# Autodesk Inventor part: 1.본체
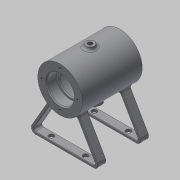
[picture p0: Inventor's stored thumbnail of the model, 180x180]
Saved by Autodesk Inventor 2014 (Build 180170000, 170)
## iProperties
Created: 2016-03
Part Number: 1.본체
Material: 일반
Document SubType Name: Modeling
Designer: SCD-A15
Density: 1 g/cm^3
Appearance: 기본값
Author: SCD-A15
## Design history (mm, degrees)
sketch "스케치1"
  geometry: C1 r 26 at (0, 0); 1 further point
  constraints: 1 centre point, 1 coincident
  dimensions: "d0" = 52 diameter of C1
extrude "돌출1" new body sketch "스케치1" stored distance "d1" = 70; taper "d2" = 0 deg
node "작업 평면1"
sketch "스케치3"
  geometry: L1 (0, 8.775)-(42.594, -65); L2 (42.594, -65)-(-42.594, -65); L3 (-42.594, -65)-(0, 8.775); L4 (0, 0)-(0, -26); L5 (37.398, -62)-(0, 2.775); L6 (0, 2.775)-(-37.398, -62); L7 (-37.398, -62)-(37.398, -62); A1 r 26 centre (0, 0) between (16.613, -20) and (0, -26) reference; 2 further points
  constraints: 14 end point, 2 point on circle, 1 coincident, 1 perpendicular, 1 point on line, 1 vertical, 1 vertical alignment, 9 other
  dimensions: "d4" = 65 distance from line of L2 point (0, 0); "d5" = 45 distance from line of L2 A1.start; "d6" = 3 distance between parallel lines of L1 L5
extrude "돌출2" join sketch "스케치3" distance "d7" = 10; taper "d8" = 0 deg
fillet "모깎기1" dims "d9" = 5
fillet "모깎기2" dims "d10" = 2
sketch "스케치10"
  geometry: L1 (0, 10)-(67.868, 10) reference; C1 r 3 at (13.934, 5); C2 r 3 at (53.934, 5); 1 further point
  constraints: 2 centre point, 1 equal radius, 1 horizontal alignment
  dimensions: "d76" = 20 horizontal distance of C1.centre point (33.934, 30); "d77" = 40 distance of C2.centre C1.centre; "d78" = 5 distance from line of L1 C2.centre; "d79" = 6 diameter of C2
extrude "돌출5" cut sketch "스케치10" stored distance "d80" = 29; taper "d81" = 0 deg
fillet "모깎기4" dims "d82" = 0.5
sketch "스케치5"
  geometry: C1 r 5 at (0, 0); 1 further point
  constraints: 1 centre point, 1 coincident
  dimensions: "d11" = 10 diameter of C1
extrude "돌출3" join sketch "스케치5" distance "d12" = 29; taper "d13" = 0 deg
sketch "스케치6"
  geometry: L1 (0, 0)-(7.506, -28.012); L2 (0, 0)-(0, -26); 2 further points
  constraints: 4 end point, 1 coincident, 1 vertical, 1 vertical alignment, 1 other
  dimensions: "d14" = 15 deg angle of L2 L1; "d15" = 29 distance of L1.start L1.end
node "작업 평면2"
sketch "스케치7"
  geometry: C1 r 6 at (0, 0); 1 further point
  constraints: 1 centre point, 1 coincident
  dimensions: "d16" = 12 diameter of C1
extrude "돌출4" join sketch "스케치7" stored distance "d17" = 29; taper "d18" = 0 deg
hole "구멍1" diameter "d21" = 28; stored, may be unused: countersink angle "d25" = 90 deg, drill point angle "d27" = 118 deg; dims "d19" = 10, "d20" = 10, "d22" = 6, "d23" = 32, "d24" = 12, "d26" = 8
hole "구멍2" diameter "d30" = 28; stored, may be unused: countersink angle "d34" = 90 deg, drill point angle "d36" = 118 deg; dims "d28" = 10, "d29" = 10, "d31" = 6, "d32" = 32, "d33" = 12, "d35" = 8
sketch "스케치8"
  geometry: C1 r 16 at (0, 0) reference; 1 further point
  constraints: 1 vertical alignment
  dimensions: "d90" = 21 distance of C1.centre point (0, 21)
hole "구멍3" sketch "스케치8" at (0, 21) diameter "d37" = 3.242; stored, may be unused: countersink angle "d41" = 90 deg, drill point angle "d43" = 118 deg; dims "d38" = 8, "d39" = 32, "d40" = 12, "d42" = 10
sketch "스케치9"
  geometry: L1 (0, 21)-(18, 21); L2 (21, 18)-(21, -18); L3 (18, -21)-(0, -21); L4 (0, -21)-(0, 21); A1 r 3 centre (18, -18) between (18, -21) and (21, -18); A2 r 3 centre (18, 18) between (21, 18) and (18, 21); 4 further points
  constraints: 8 end point, 4 point on circle, 4 point on line, 4 tangent, 2 centre point, 2 parallel, 1 coincident, 1 equal radius, 1 horizontal, 1 midpoint, 1 perpendicular
  dimensions: "d47" = 42 distance of point (21, 21) point (21, -21); "d49" = 42 diameter of L2 L4; "d50" = 3 radius of A1
revolve "회전1" sketch "스케치9" stored, may be unused: angle "d51" = 90 deg
chamfer "모따기1" distance "d52" = 1; stored, may be unused: second distance "d53" = 2, angle "d54" = 45 deg
hole "구멍4" diameter "d57" = 5.188; stored, may be unused: countersink angle "d61" = 90 deg, drill point angle "d63" = 118 deg; dims "d58" = 8, "d59" = 32, "d60" = 12, "d62" = 10, "d64" = 10, "d65" = 10
hole "구멍5" diameter "d68" = 5.188; stored, may be unused: countersink angle "d72" = 90 deg, drill point angle "d74" = 118 deg; dims "d66" = 10, "d67" = 10, "d69" = 8, "d70" = 32, "d71" = 12, "d73" = 10
fillet "모깎기3" dims "d75" = 0.3
node "작업 평면3"
fillet "모깎기5" dims "d86" = 3
node "작업 평면4"
sketch "스케치15"
  geometry: 2 further points
  constraints: 1 coincident, 1 other
feature "엠보싱2" sketch "스케치15" dims "d88" = 0.5, "d89" = 0
node "솔리드1"
mirror "대칭1"
pattern_circular "원형 패턴1" dims angle "d45" = 360 deg
mirror "대칭2"
